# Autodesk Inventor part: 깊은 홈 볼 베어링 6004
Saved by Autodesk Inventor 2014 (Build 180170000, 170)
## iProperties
Created: 2026-04
Part Number: 깊은 홈 볼 베어링 6004
Material: 일반
Document SubType Name: Modeling
Designer: dg
Density: 1 g/cm^3
Appearance: 기본값
Author: dg
Author: jhkim
Description: 깊은 그루브 볼 베어링
Creation Date: 2026-03-27
Sending System: Autodesk Inventor 2026
Preprocessor: ST-DEVELOPER v20.1
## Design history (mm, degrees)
node "깊은 홈 볼 베어링 60041"
body "Solid1"
node "Solid1_1"
node "Solid1_2"
node "Solid1_3"
node "Solid1_4"
node "Solid1_5"
node "Solid1_6"
node "Solid1_7"
node "Solid1_8"
node "Solid1_9"
node "Solid1_10"
node "기준1"
node "기준2"
node "기준3"
node "기준4"
node "기준5"
node "기준6"
node "기준7"
node "기준8"
node "기준9"
node "기준10"
node "기준11"
